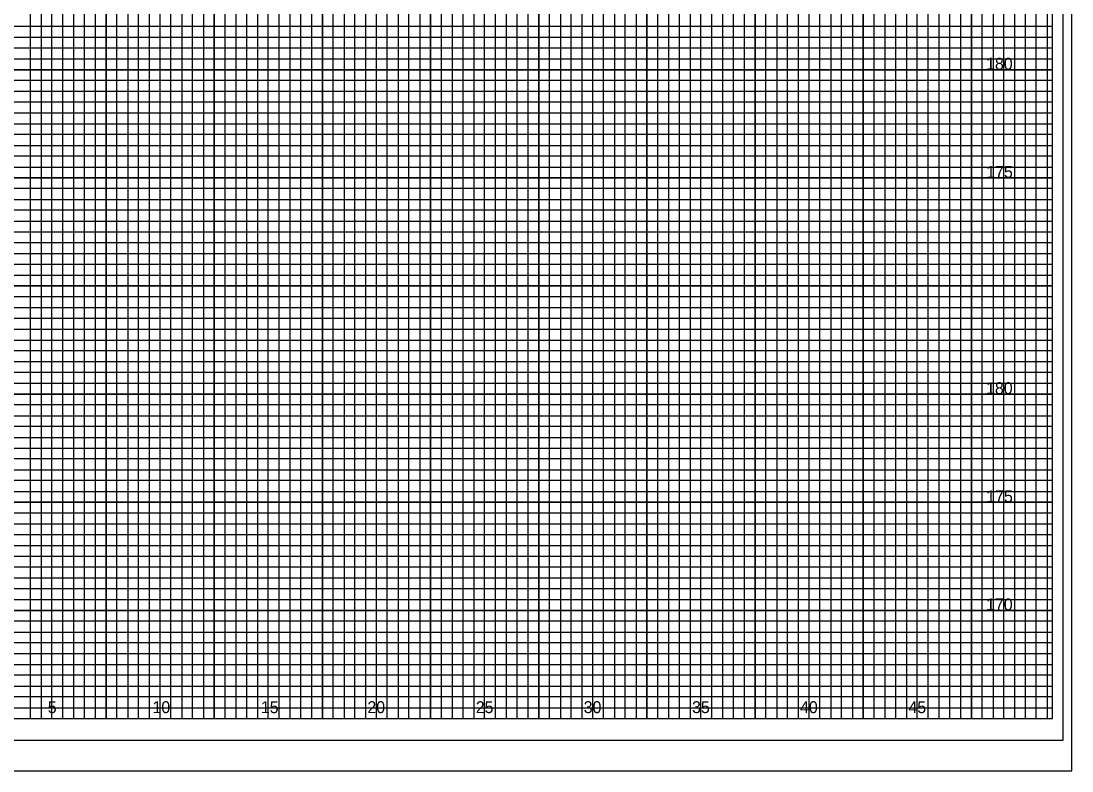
# Model space of a CAD drawing. Extents: x -4 to 103, y -2 to 280.
# Drawn here: x 54.82 to 103.4, y 68.4 to 103.08 of the extents above; entities that cross this region are included whole.
import ezdxf

# ---------------------------------------------------------------- set-up
doc = ezdxf.new("R2010")
doc.units = 0
for name, color, linetype in [('Exist XS Center Line Elevation Label', 7, 'Continuous'), ('Old_Level_63', 7, 'Continuous'), ('Prop XS Dump Level', 7, 'Continuous'), ('Prop XS Pvmt Edge Slope', 7, 'Continuous'), ('Prop XS SE Text', 7, 'Continuous'), ('Prop XS Subgrade Earthwork', 7, 'Continuous'), ('Sheet Cutting Line CELL', 7, 'Continuous'), ('Sheet Plot Border Inside CELL', 7, 'Continuous'), ('Sheet Plot Border Outside CELL', 7, 'Continuous')]:
    doc.layers.add(name, color=color, linetype=linetype)

msp = doc.modelspace()

# ---------------------------------------------------------------- linework, layer by layer
at = {"layer": 'Exist XS Center Line Elevation Label'}
for points in [[(56.25, 70.825), (56.25, 135.825)], [(58.75, 135.825), (58.75, 70.825), (61.25, 70.825), (61.25, 135.825)], [(63.75, 135.825), (63.75, 70.825), (66.25, 70.825), (66.25, 135.825)], [(68.75, 135.825), (68.75, 70.825), (71.25, 70.825), (71.25, 135.825)], [(73.75, 135.825), (73.75, 70.825), (76.25, 70.825), (76.25, 132.825)], [(88.75, 132.825), (88.75, 70.825), (91.25, 70.825), (91.25, 134.25)], [(93.75, 134.25), (93.75, 70.825), (96.25, 70.825), (96.25, 134.25)], [(98.75, 134.25), (98.75, 70.825), (101.25, 70.825), (101.25, 134.25)], [(78.75, 132.825), (78.75, 70.825), (81.25, 70.825), (81.25, 132.825)], [(83.75, 132.825), (83.75, 70.825), (86.25, 70.825), (86.25, 132.825)], [(0, 98.325), (102.5, 98.325), (102.5, 100.825), (0, 100.825)], [(0, 93.325), (102.5, 93.325), (102.5, 95.825), (0, 95.825)], [(0, 88.325), (102.5, 88.325), (102.5, 90.825), (0, 90.825)], [(0, 83.325), (102.5, 83.325), (102.5, 85.825), (0, 85.825)], [(0, 78.325), (102.5, 78.325), (102.5, 80.825), (0, 80.825)], [(0, 73.325), (102.5, 73.325), (102.5, 75.825), (0, 75.825)]]:
    msp.add_lwpolyline(points, dxfattribs=at)
at = {"layer": 'Old_Level_63'}
msp.add_lwpolyline([(102.5, 135.825), (0, 135.825), (0, 70.825), (102.5, 70.825)], close=True, dxfattribs=at)
at = {"layer": 'Prop XS Dump Level'}
for p, q in [((56.25, 70.825), (56.25, 135.825)), ((58.75, 70.825), (58.75, 135.825)), ((61.25, 70.825), (61.25, 135.825)), ((63.75, 70.825), (63.75, 135.825)), ((66.25, 70.825), (66.25, 135.825)), ((68.75, 70.825), (68.75, 135.825)), ((71.25, 70.825), (71.25, 135.825)), ((73.75, 70.825), (73.75, 135.825)), ((91.25, 70.825), (91.25, 134.25)), ((93.75, 70.825), (93.75, 134.25)), ((96.25, 70.825), (96.25, 134.25)), ((98.75, 70.825), (98.75, 134.25)), ((101.25, 70.825), (101.25, 134.25)), ((76.25, 70.825), (76.25, 132.825)), ((78.75, 70.825), (78.75, 132.825)), ((81.25, 70.825), (81.25, 132.825)), ((83.75, 70.825), (83.75, 132.825)), ((86.25, 70.825), (86.25, 132.825)), ((88.75, 70.825), (88.75, 132.825)), ((0, 100.825), (102.5, 100.825)), ((0, 98.325), (102.5, 98.325)), ((0, 95.825), (102.5, 95.825)), ((0, 93.325), (102.5, 93.325)), ((0, 90.825), (102.5, 90.825)), ((0, 88.325), (102.5, 88.325)), ((0, 85.825), (102.5, 85.825)), ((0, 83.325), (102.5, 83.325)), ((0, 80.825), (102.5, 80.825)), ((0, 78.325), (102.5, 78.325)), ((0, 75.825), (102.5, 75.825)), ((0, 73.325), (102.5, 73.325))]:
    msp.add_line(p, q, dxfattribs=at)
at = {"layer": 'Prop XS SE Text'}
for points in [[(54.75, 70.825), (55.25, 70.825), (55.25, 135.825)], [(55.75, 135.825), (55.75, 70.825), (56.75, 70.825), (56.75, 135.825)], [(57.25, 135.825), (57.25, 70.825), (57.75, 70.825), (57.75, 135.825)], [(58.25, 135.825), (58.25, 70.825), (59.25, 70.825), (59.25, 135.825)], [(59.75, 135.825), (59.75, 70.825), (60.25, 70.825), (60.25, 135.825)], [(60.75, 135.825), (60.75, 70.825), (61.75, 70.825), (61.75, 135.825)], [(62.25, 135.825), (62.25, 70.825), (62.75, 70.825), (62.75, 135.825)], [(63.25, 135.825), (63.25, 70.825), (64.25, 70.825), (64.25, 135.825)], [(64.75, 135.825), (64.75, 70.825), (65.25, 70.825), (65.25, 135.825)], [(65.75, 135.825), (65.75, 70.825), (66.75, 70.825), (66.75, 135.825)], [(67.25, 135.825), (67.25, 70.825), (67.75, 70.825), (67.75, 135.825)], [(68.25, 135.825), (68.25, 70.825), (69.25, 70.825), (69.25, 135.825)], [(69.75, 135.825), (69.75, 70.825), (70.25, 70.825), (70.25, 135.825)], [(70.75, 135.825), (70.75, 70.825), (71.75, 70.825), (71.75, 135.825)], [(72.25, 135.825), (72.25, 70.825), (72.75, 70.825), (72.75, 135.825)], [(73.25, 135.825), (73.25, 70.825), (74.25, 70.825), (74.25, 132.825)], [(89.75, 132.825), (89.75, 70.825), (90.25, 70.825), (90.25, 134.25)], [(90.75, 134.25), (90.75, 70.825), (91.75, 70.825), (91.75, 134.25)], [(92.25, 134.25), (92.25, 70.825), (92.75, 70.825), (92.75, 134.25)], [(93.25, 134.25), (93.25, 70.825), (94.25, 70.825), (94.25, 134.25)], [(94.75, 134.25), (94.75, 70.825), (95.25, 70.825), (95.25, 134.25)], [(95.75, 134.25), (95.75, 70.825), (96.75, 70.825), (96.75, 134.25)], [(97.25, 134.25), (97.25, 70.825), (97.75, 70.825), (97.75, 134.25)], [(98.25, 134.25), (98.25, 70.825), (99.25, 70.825), (99.25, 134.25)], [(99.75, 134.25), (99.75, 70.825), (100.25, 70.825), (100.25, 134.25)], [(100.25, 134.25), (100.75, 134.25), (100.75, 70.825), (101.75, 70.825), (101.75, 134.25), (102.25, 134.25), (102.25, 70.825)], [(74.75, 132.825), (74.75, 70.825), (75.25, 70.825), (75.25, 132.825)], [(75.75, 132.825), (75.75, 70.825), (76.75, 70.825), (76.75, 132.825)], [(77.25, 132.825), (77.25, 70.825), (77.75, 70.825), (77.75, 132.825)], [(78.25, 132.825), (78.25, 70.825), (79.25, 70.825), (79.25, 132.825)], [(79.75, 132.825), (79.75, 70.825), (80.25, 70.825), (80.25, 132.825)], [(80.75, 132.825), (80.75, 70.825), (81.75, 70.825), (81.75, 132.825)], [(82.25, 132.825), (82.25, 70.825), (82.75, 70.825), (82.75, 132.825)], [(83.25, 132.825), (83.25, 70.825), (84.25, 70.825), (84.25, 132.825)], [(84.75, 132.825), (84.75, 70.825), (85.25, 70.825), (85.25, 132.825)], [(85.75, 132.825), (85.75, 70.825), (86.75, 70.825), (86.75, 132.825)], [(87.25, 132.825), (87.25, 70.825), (87.75, 70.825), (87.75, 132.825)], [(88.25, 132.825), (88.25, 70.825), (89.25, 70.825), (89.25, 132.825)], [(0, 102.325), (102.5, 102.325), (102.5, 102.825), (0, 102.825)], [(0, 101.325), (102.5, 101.325), (102.5, 101.825), (0, 101.825)], [(0, 99.825), (102.5, 99.825), (102.5, 100.325), (0, 100.325)], [(0, 98.825), (102.5, 98.825), (102.5, 99.325), (0, 99.325)], [(0, 97.325), (102.5, 97.325), (102.5, 97.825), (0, 97.825)], [(0, 96.325), (102.5, 96.325), (102.5, 96.825), (0, 96.825)], [(0, 94.825), (102.5, 94.825), (102.5, 95.325), (0, 95.325)], [(0, 93.825), (102.5, 93.825), (102.5, 94.325), (0, 94.325)], [(0, 92.325), (102.5, 92.325), (102.5, 92.825), (0, 92.825)], [(0, 91.325), (102.5, 91.325), (102.5, 91.825), (0, 91.825)], [(0, 89.825), (102.5, 89.825), (102.5, 90.325), (0, 90.325)], [(0, 88.825), (102.5, 88.825), (102.5, 89.325), (0, 89.325)], [(0, 87.325), (102.5, 87.325), (102.5, 87.825), (0, 87.825)], [(0, 86.325), (102.5, 86.325), (102.5, 86.825), (0, 86.825)], [(0, 84.825), (102.5, 84.825), (102.5, 85.325), (0, 85.325)], [(0, 83.825), (102.5, 83.825), (102.5, 84.325), (0, 84.325)], [(0, 82.325), (102.5, 82.325), (102.5, 82.825), (0, 82.825)], [(0, 81.325), (102.5, 81.325), (102.5, 81.825), (0, 81.825)], [(0, 79.825), (102.5, 79.825), (102.5, 80.325), (0, 80.325)], [(0, 78.825), (102.5, 78.825), (102.5, 79.325), (0, 79.325)], [(0, 77.325), (102.5, 77.325), (102.5, 77.825), (0, 77.825)], [(0, 76.325), (102.5, 76.325), (102.5, 76.825), (0, 76.825)], [(0, 74.825), (102.5, 74.825), (102.5, 75.325), (0, 75.325)], [(0, 73.825), (102.5, 73.825), (102.5, 74.325), (0, 74.325)], [(0, 72.325), (102.5, 72.325), (102.5, 72.825), (0, 72.825)], [(0, 71.325), (102.5, 71.325), (102.5, 71.825), (0, 71.825)]]:
    msp.add_lwpolyline(points, dxfattribs=at)
at = {"layer": 'Sheet Cutting Line CELL'}
msp.add_line((-3.5, 68.4), (103.4, 68.4), dxfattribs=at)
at = {"layer": 'Sheet Plot Border Inside CELL'}
msp.add_lwpolyline([(103, 136.825), (-2.8, 136.825), (-2.8, 69.825), (103, 69.825)], close=True, dxfattribs=at)
at = {"layer": 'Sheet Plot Border Outside CELL'}
msp.add_lwpolyline([(103.4, 138.225), (-3.5, 138.225), (-3.5, 68.4), (103.4, 68.4)], close=True, dxfattribs=at)

# ---------------------------------------------------------------- texts
at = {"layer": 'Prop XS Pvmt Edge Slope'}
for s, p in [('5', (56.057, 71.075)), ('10', (60.897, 71.075)), ('15', (65.906, 71.075)), ('20', (70.831, 71.075)), ('25', (75.84, 71.075)), ('30', (80.831, 71.075)), ('35', (85.84, 71.075)), ('40', (90.831, 71.075)), ('45', (95.84, 71.075))]:
    msp.add_text(s, height=0.55, dxfattribs=at).set_placement(p)
at = {"layer": 'Prop XS Subgrade Earthwork'}
for s, p in [('180', (99.43, 100.825)), ('175', (99.438, 95.825)), ('180', (99.43, 85.825)), ('175', (99.438, 80.825)), ('170', (99.43, 75.825))]:
    msp.add_text(s, height=0.55, dxfattribs=at).set_placement(p)

doc.saveas('drawing.dxf')
